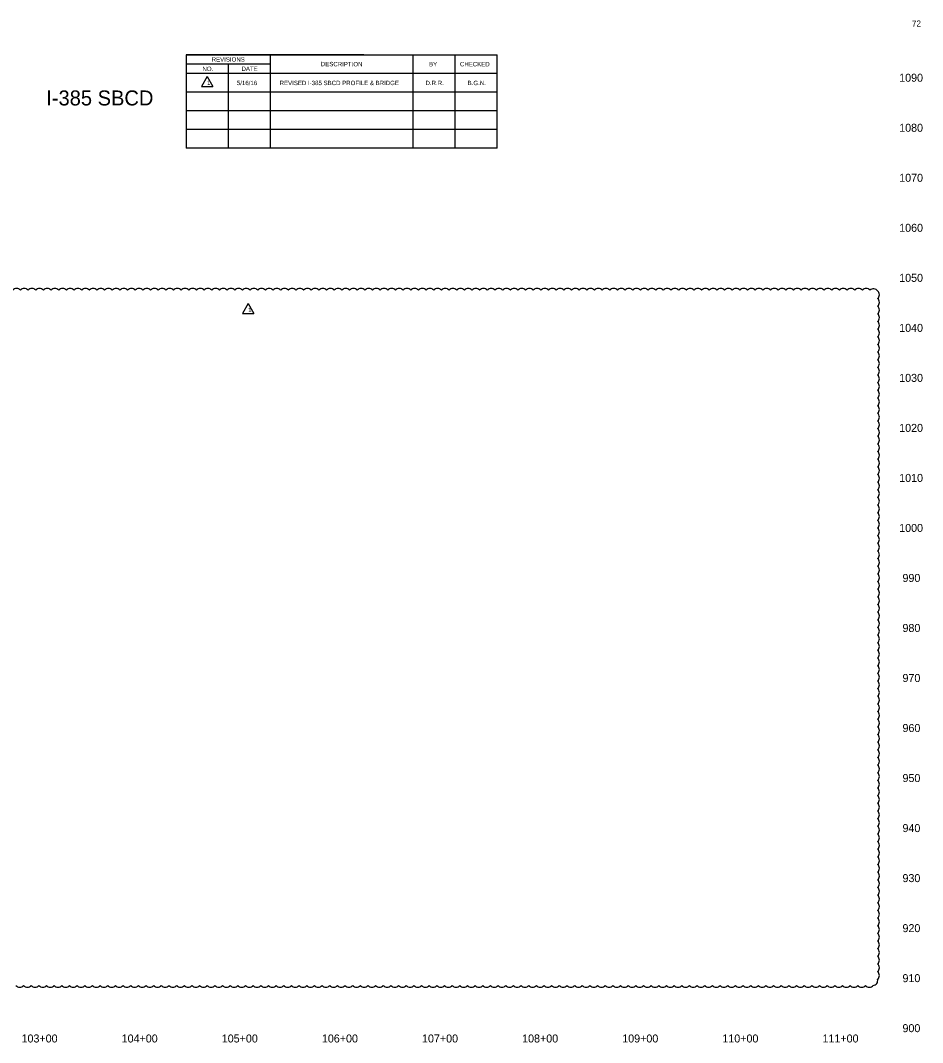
# Model space of a CAD drawing. Extents: x 16972803 to 16974463, y 12564277 to 12565299.
# Drawn here: x 16973562 to 16974463, y 12564277 to 12565299 of the extents above; entities that cross this region are included whole.
import ezdxf

# ---------------------------------------------------------------- set-up
doc = ezdxf.new("R2010")
doc.units = 0
for name, color, linetype in [('RD_DDB_ElevTX', 7, 'Continuous'), ('RD_DDB_StaTX', 7, 'Continuous'), ('RD_SHT_TX', 7, 'Continuous')]:
    doc.layers.add(name, color=color, linetype=linetype)

msp = doc.modelspace()

# ---------------------------------------------------------------- linework, layer by layer
at = {"layer": 'RD_SHT_TX'}
for p, q in [((16973728.1, 12565264.8), (16974038.7, 12565264.8)), ((16973905.4, 12565264.8), (16973728.1, 12565264.8)), ((16973728.1, 12565264.8), (16973728.1, 12565171.3)), ((16973812.1, 12565171.3), (16973812.1, 12565264.8)), ((16973954.7, 12565171.3), (16973954.7, 12565264.8)), ((16973996.7, 12565171.3), (16973996.7, 12565264.8)), ((16974038.7, 12565171.3), (16974038.7, 12565264.8)), ((16973812.1, 12565255.4), (16973728.1, 12565255.4)), ((16973770.1, 12565171.3), (16973770.1, 12565255.4)), ((16974038.7, 12565246.1), (16973728.1, 12565246.1)), ((16973748.8, 12565243.1), (16973743.1, 12565233)), ((16973748.8, 12565243.1), (16973754.5, 12565233)), ((16973743.1, 12565233), (16973754.5, 12565233)), ((16974038.7, 12565227.4), (16973728.1, 12565227.4)), ((16974038.7, 12565208.7), (16973728.1, 12565208.7)), ((16974038.7, 12565190), (16973728.1, 12565190)), ((16974038.7, 12565171.3), (16973728.1, 12565171.3)), ((16973789.9, 12565016.1), (16973784.2, 12565006)), ((16973789.9, 12565016.1), (16973795.6, 12565006)), ((16973784.2, 12565006), (16973795.6, 12565006))]:
    msp.add_line(p, q, dxfattribs=at)
for centre, start, end in [((16973558.6, 12565026.3), 40, 140), ((16973566.2, 12565026.3), 40, 140), ((16973573.9, 12565026.3), 40, 140), ((16973581.5, 12565026.3), 40, 140), ((16973589.2, 12565026.3), 40, 140), ((16973596.8, 12565026.3), 40, 140), ((16973604.5, 12565026.3), 40, 140), ((16973612.1, 12565026.3), 40, 140), ((16973619.8, 12565026.3), 40, 140), ((16973627.4, 12565026.3), 40, 140), ((16973635, 12565026.3), 40, 140), ((16973642.7, 12565026.3), 40, 140), ((16973650.3, 12565026.3), 40, 140), ((16973658, 12565026.3), 40, 140), ((16973665.6, 12565026.3), 40, 140), ((16973673.3, 12565026.3), 40, 140), ((16973680.9, 12565026.3), 40, 140), ((16973688.6, 12565026.3), 40, 140), ((16973696.2, 12565026.3), 40, 140), ((16973703.9, 12565026.3), 40, 140), ((16973711.5, 12565026.3), 40, 140), ((16973719.1, 12565026.3), 40, 140), ((16973726.8, 12565026.3), 40, 140), ((16973734.4, 12565026.3), 40, 140), ((16973742.1, 12565026.3), 40, 140), ((16973749.7, 12565026.3), 40, 140), ((16973757.4, 12565026.3), 40, 140), ((16973765, 12565026.3), 40, 140), ((16973772.7, 12565026.3), 40, 140), ((16973780.3, 12565026.3), 40, 140), ((16973787.9, 12565026.3), 40, 140), ((16973795.6, 12565026.3), 40, 140), ((16973803.2, 12565026.3), 40, 140), ((16973810.9, 12565026.3), 40, 140), ((16973818.5, 12565026.3), 40, 140), ((16973826.2, 12565026.3), 40, 140), ((16973833.8, 12565026.3), 40, 140), ((16973841.5, 12565026.3), 40, 140), ((16973849.1, 12565026.3), 40, 140), ((16973856.7, 12565026.3), 40, 140), ((16973864.4, 12565026.3), 40, 140), ((16973872, 12565026.3), 40, 140), ((16973879.7, 12565026.3), 40, 140), ((16973887.3, 12565026.3), 40, 140), ((16973895, 12565026.3), 40, 140), ((16973902.6, 12565026.3), 40, 140), ((16973910.3, 12565026.3), 40, 140), ((16973917.9, 12565026.3), 40, 140), ((16973925.5, 12565026.3), 40, 140), ((16973933.2, 12565026.3), 40, 140), ((16973940.8, 12565026.3), 40, 140), ((16973948.5, 12565026.3), 40, 140), ((16973956.1, 12565026.3), 40, 140), ((16973963.8, 12565026.3), 40, 140), ((16973971.4, 12565026.3), 40, 140), ((16973979.1, 12565026.3), 40, 140), ((16973986.7, 12565026.3), 40, 140), ((16973994.3, 12565026.3), 40, 140), ((16974002, 12565026.3), 40, 140), ((16974009.6, 12565026.3), 40, 140), ((16974017.3, 12565026.3), 40, 140), ((16974024.9, 12565026.3), 40, 140), ((16974032.6, 12565026.3), 40, 140), ((16974040.2, 12565026.3), 40, 140), ((16974047.9, 12565026.3), 40, 140), ((16974055.5, 12565026.3), 40, 140), ((16974063.1, 12565026.3), 40, 140), ((16974070.8, 12565026.3), 40, 140), ((16974078.4, 12565026.3), 40, 140), ((16974086.1, 12565026.3), 40, 140), ((16974093.7, 12565026.3), 40, 140), ((16974101.4, 12565026.3), 40, 140), ((16974109, 12565026.3), 40, 140), ((16974116.7, 12565026.3), 40, 140), ((16974124.3, 12565026.3), 40, 140), ((16974131.9, 12565026.3), 40, 140), ((16974139.6, 12565026.3), 40, 140), ((16974147.2, 12565026.3), 40, 140), ((16974154.9, 12565026.3), 40, 140), ((16974162.5, 12565026.3), 40, 140), ((16974170.2, 12565026.3), 40, 140), ((16974177.8, 12565026.3), 40, 140), ((16974185.5, 12565026.3), 40, 140), ((16974193.1, 12565026.3), 40, 140), ((16974200.7, 12565026.3), 40, 140), ((16974208.4, 12565026.3), 40, 140), ((16974216, 12565026.3), 40, 140), ((16974223.7, 12565026.3), 40, 140), ((16974231.3, 12565026.3), 40, 140), ((16974239, 12565026.3), 40, 140), ((16974246.6, 12565026.3), 40, 140), ((16974254.3, 12565026.3), 40, 140), ((16974261.9, 12565026.3), 40, 140), ((16974269.5, 12565026.3), 40, 140), ((16974277.2, 12565026.3), 40, 140), ((16974284.8, 12565026.3), 40, 140), ((16974292.5, 12565026.3), 40, 140), ((16974300.1, 12565026.3), 40, 140), ((16974307.8, 12565026.3), 40, 140), ((16974315.4, 12565026.3), 40, 140), ((16974323.1, 12565026.3), 40, 140), ((16974330.7, 12565026.3), 40, 140), ((16974338.4, 12565026.3), 40, 140), ((16974346, 12565026.3), 40, 140), ((16974353.6, 12565026.3), 40, 140), ((16974361.3, 12565026.3), 40, 140), ((16974368.9, 12565026.3), 40, 140), ((16974376.6, 12565026.3), 40, 140), ((16974384.2, 12565026.3), 40, 140), ((16974391.9, 12565026.3), 40, 140), ((16974399.5, 12565026.3), 40, 140), ((16974407.2, 12565026.3), 40, 140), ((16974414.4, 12565025.9), 34.0741, 134.0741), ((16974415.4, 12565024.9), 310, 50), ((16974415.4, 12565017.3), 310, 50), ((16974415.4, 12565009.6), 310, 50), ((16974415.4, 12565002), 310, 50), ((16974415.4, 12564994.3), 310, 50), ((16974415.4, 12564986.7), 310, 50), ((16974415.4, 12564979), 310, 50), ((16974415.4, 12564971.4), 310, 50), ((16974415.4, 12564963.8), 310, 50), ((16974415.4, 12564956.1), 310, 50), ((16974415.4, 12564948.5), 310, 50), ((16974415.4, 12564940.8), 310, 50), ((16974415.4, 12564933.2), 310, 50), ((16974415.4, 12564925.5), 310, 50), ((16974415.4, 12564917.9), 310, 50), ((16974415.4, 12564910.2), 310, 50), ((16974415.4, 12564902.6), 310, 50), ((16974415.4, 12564895), 310, 50), ((16974415.4, 12564887.3), 310, 50), ((16974415.4, 12564879.7), 310, 50), ((16974415.4, 12564872), 310, 50), ((16974415.4, 12564864.4), 310, 50), ((16974415.4, 12564856.7), 310, 50), ((16974415.4, 12564849.1), 310, 50), ((16974415.4, 12564841.4), 310, 50), ((16974415.4, 12564833.8), 310, 50), ((16974415.4, 12564826.2), 310, 50), ((16974415.4, 12564818.5), 310, 50), ((16974415.4, 12564810.9), 310, 50), ((16974415.4, 12564803.2), 310, 50), ((16974415.4, 12564795.6), 310, 50), ((16974415.4, 12564787.9), 310, 50), ((16974415.4, 12564780.3), 310, 50), ((16974415.4, 12564772.6), 310, 50), ((16974415.4, 12564765), 310, 50), ((16974415.4, 12564757.4), 310, 50), ((16974415.4, 12564749.7), 310, 50), ((16974415.4, 12564742.1), 310, 50), ((16974415.4, 12564734.4), 310, 50), ((16974415.4, 12564726.8), 310, 50), ((16974415.4, 12564719.1), 310, 50), ((16974415.4, 12564711.5), 310, 50), ((16974415.4, 12564703.8), 310, 50), ((16974415.4, 12564696.2), 310, 50), ((16974415.4, 12564688.6), 310, 50), ((16974415.4, 12564680.9), 310, 50), ((16974415.4, 12564673.3), 310, 50), ((16974415.4, 12564665.6), 310, 50), ((16974415.4, 12564658), 310, 50), ((16974415.4, 12564650.3), 310, 50), ((16974415.4, 12564642.7), 310, 50), ((16974415.4, 12564635), 310, 50), ((16974415.4, 12564627.4), 310, 50), ((16974415.4, 12564619.8), 310, 50), ((16974415.4, 12564612.1), 310, 50), ((16974415.4, 12564604.5), 310, 50), ((16974415.4, 12564596.8), 310, 50), ((16974415.4, 12564589.2), 310, 50), ((16974415.4, 12564581.5), 310, 50), ((16974415.4, 12564573.9), 310, 50), ((16974415.4, 12564566.2), 310, 50), ((16974415.4, 12564558.6), 310, 50), ((16974415.4, 12564550.9), 310, 50), ((16974415.4, 12564543.3), 310, 50), ((16974415.4, 12564535.7), 310, 50), ((16974415.4, 12564528), 310, 50), ((16974415.4, 12564520.4), 310, 50), ((16974415.4, 12564512.7), 310, 50), ((16974415.4, 12564505.1), 310, 50), ((16974415.4, 12564497.4), 310, 50), ((16974415.4, 12564489.8), 310, 50), ((16974415.4, 12564482.1), 310, 50), ((16974415.4, 12564474.5), 310, 50), ((16974415.4, 12564466.9), 310, 50), ((16974415.4, 12564459.2), 310, 50), ((16974415.4, 12564451.6), 310, 50), ((16974415.4, 12564443.9), 310, 50), ((16974415.4, 12564436.3), 310, 50), ((16974415.4, 12564428.6), 310, 50), ((16974415.4, 12564421), 310, 50), ((16974415.4, 12564413.3), 310, 50), ((16974415.4, 12564405.7), 310, 50), ((16974415.4, 12564398.1), 310, 50), ((16974415.4, 12564390.4), 310, 50), ((16974415.4, 12564382.8), 310, 50), ((16974415.4, 12564375.1), 310, 50), ((16974415.4, 12564367.5), 310, 50), ((16974415.4, 12564359.8), 310, 50), ((16974415.4, 12564352.2), 310, 50), ((16974415.4, 12564344.5), 310, 50), ((16973561.7, 12564337.7), 220, 320), ((16973569.4, 12564337.7), 220, 320), ((16973577, 12564337.7), 220, 320), ((16973584.7, 12564337.7), 220, 320), ((16973592.3, 12564337.7), 220, 320), ((16973599.9, 12564337.7), 220, 320), ((16973607.6, 12564337.7), 220, 320), ((16973615.2, 12564337.7), 220, 320), ((16973622.9, 12564337.7), 220, 320), ((16973630.5, 12564337.7), 220, 320), ((16973638.2, 12564337.7), 220, 320), ((16973645.8, 12564337.7), 220, 320), ((16973653.5, 12564337.7), 220, 320), ((16973661.1, 12564337.7), 220, 320), ((16973668.7, 12564337.7), 220, 320), ((16973676.4, 12564337.7), 220, 320), ((16973684, 12564337.7), 220, 320), ((16973691.7, 12564337.7), 220, 320), ((16973699.3, 12564337.7), 220, 320), ((16973707, 12564337.7), 220, 320), ((16973714.6, 12564337.7), 220, 320), ((16973722.3, 12564337.7), 220, 320), ((16973729.9, 12564337.7), 220, 320), ((16973737.6, 12564337.7), 220, 320), ((16973745.2, 12564337.7), 220, 320), ((16973752.8, 12564337.7), 220, 320), ((16973760.5, 12564337.7), 220, 320), ((16973768.1, 12564337.7), 220, 320), ((16973775.8, 12564337.7), 220, 320), ((16973783.4, 12564337.7), 220, 320), ((16973791.1, 12564337.7), 220, 320), ((16973798.7, 12564337.7), 220, 320), ((16973806.4, 12564337.7), 220, 320), ((16973814, 12564337.7), 220, 320), ((16973821.6, 12564337.7), 220, 320), ((16973829.3, 12564337.7), 220, 320), ((16973836.9, 12564337.7), 220, 320), ((16973844.6, 12564337.7), 220, 320), ((16973852.2, 12564337.7), 220, 320), ((16973859.9, 12564337.7), 220, 320), ((16973867.5, 12564337.7), 220, 320), ((16973875.2, 12564337.7), 220, 320), ((16973882.8, 12564337.7), 220, 320), ((16973890.4, 12564337.7), 220, 320), ((16973898.1, 12564337.7), 220, 320), ((16973905.7, 12564337.7), 220, 320), ((16973913.4, 12564337.7), 220, 320), ((16973921, 12564337.7), 220, 320), ((16973928.7, 12564337.7), 220, 320), ((16973936.3, 12564337.7), 220, 320), ((16973944, 12564337.7), 220, 320), ((16973951.6, 12564337.7), 220, 320), ((16973959.2, 12564337.7), 220, 320), ((16973966.9, 12564337.7), 220, 320), ((16973974.5, 12564337.7), 220, 320), ((16973982.2, 12564337.7), 220, 320), ((16973989.8, 12564337.7), 220, 320), ((16973997.5, 12564337.7), 220, 320), ((16974005.1, 12564337.7), 220, 320), ((16974012.8, 12564337.7), 220, 320), ((16974020.4, 12564337.7), 220, 320), ((16974028, 12564337.7), 220, 320), ((16974035.7, 12564337.7), 220, 320), ((16974043.3, 12564337.7), 220, 320), ((16974051, 12564337.7), 220, 320), ((16974058.6, 12564337.7), 220, 320), ((16974066.3, 12564337.7), 220, 320), ((16974073.9, 12564337.7), 220, 320), ((16974081.6, 12564337.7), 220, 320), ((16974089.2, 12564337.7), 220, 320), ((16974096.8, 12564337.7), 220, 320), ((16974104.5, 12564337.7), 220, 320), ((16974112.1, 12564337.7), 220, 320), ((16974119.8, 12564337.7), 220, 320), ((16974127.4, 12564337.7), 220, 320), ((16974135.1, 12564337.7), 220, 320), ((16974142.7, 12564337.7), 220, 320), ((16974150.4, 12564337.7), 220, 320), ((16974158, 12564337.7), 220, 320), ((16974165.6, 12564337.7), 220, 320), ((16974173.3, 12564337.7), 220, 320), ((16974180.9, 12564337.7), 220, 320), ((16974188.6, 12564337.7), 220, 320), ((16974196.2, 12564337.7), 220, 320), ((16974203.9, 12564337.7), 220, 320), ((16974211.5, 12564337.7), 220, 320), ((16974219.2, 12564337.7), 220, 320), ((16974226.8, 12564337.7), 220, 320), ((16974234.4, 12564337.7), 220, 320), ((16974242.1, 12564337.7), 220, 320), ((16974249.7, 12564337.7), 220, 320), ((16974257.4, 12564337.7), 220, 320), ((16974265, 12564337.7), 220, 320), ((16974272.7, 12564337.7), 220, 320), ((16974280.3, 12564337.7), 220, 320), ((16974288, 12564337.7), 220, 320), ((16974295.6, 12564337.7), 220, 320), ((16974303.2, 12564337.7), 220, 320), ((16974310.9, 12564337.7), 220, 320), ((16974318.5, 12564337.7), 220, 320), ((16974326.2, 12564337.7), 220, 320), ((16974333.8, 12564337.7), 220, 320), ((16974341.5, 12564337.7), 220, 320), ((16974349.1, 12564337.7), 220, 320), ((16974356.8, 12564337.7), 220, 320), ((16974364.4, 12564337.7), 220, 320), ((16974372.1, 12564337.7), 220, 320), ((16974379.7, 12564337.7), 220, 320), ((16974387.3, 12564337.7), 220, 320), ((16974395, 12564337.7), 220, 320), ((16974402.6, 12564337.7), 220, 320), ((16974410.3, 12564337.7), 220, 320), ((16974413.7, 12564339.5), 274.0608, 14.0608)]:
    msp.add_arc(centre, 4.99, start, end, dxfattribs=at)

# ---------------------------------------------------------------- texts
at = {"layer": 'RD_DDB_ElevTX'}
for s, p in [('1090', (16974440.1, 12565237.8)), ('1080', (16974440.1, 12565187.8)), ('1070', (16974440.1, 12565137.8)), ('1060', (16974440.1, 12565087.8)), ('1050', (16974440.1, 12565037.8)), ('1040', (16974440.1, 12564987.8)), ('1030', (16974440.1, 12564937.8)), ('1020', (16974440.1, 12564887.8)), ('1010', (16974440.1, 12564837.8)), ('1000', (16974440.1, 12564787.8)), ('990', (16974443.4, 12564737.8)), ('980', (16974443.4, 12564687.8)), ('970', (16974443.4, 12564637.8)), ('960', (16974443.4, 12564587.8)), ('950', (16974443.4, 12564537.8)), ('940', (16974443.4, 12564487.8)), ('930', (16974443.4, 12564437.8)), ('920', (16974443.4, 12564387.8)), ('910', (16974443.4, 12564337.8)), ('900', (16974443.4, 12564287.8))]:
    msp.add_text(s, height=8, dxfattribs=at).set_placement(p)
at = {"layer": 'RD_DDB_StaTX'}
for s, p in [('103+00', (16973563.5, 12564277.5)), ('104+00', (16973663.5, 12564277.5)), ('105+00', (16973763.5, 12564277.5)), ('106+00', (16973863.5, 12564277.5)), ('107+00', (16973963.5, 12564277.5)), ('108+00', (16974063.5, 12564277.5)), ('109+00', (16974163.5, 12564277.5)), ('110+00', (16974263.5, 12564277.5)), ('111+00', (16974363.5, 12564277.5))]:
    msp.add_text(s, height=8, dxfattribs=at).set_placement(p)
at = {"layer": 'RD_SHT_TX'}
for s, height, p in [('72', 6, (16974452.9, 12565293)), ('REVISIONS', 4.4, (16973753.4, 12565257.9)), ('NO.', 4.4, (16973744.2, 12565248.5)), ('CHECKED', 4.4, (16974001.4, 12565253.2)), ('1', 4.4, (16973748.8, 12565234.6)), ('5/16/16', 4.4, (16973778.6, 12565234.4)), ('REVISED I-385 SBCD PROFILE & BRIDGE', 4.4, (16973821.3, 12565234.4)), ('D.R.R.', 4.4, (16973967, 12565234.4)), ('B.G.N.', 4.4, (16974009.1, 12565234.4)), ('I-385 SBCD', 15, (16973588.2, 12565214.1)), ('1', 4.4, (16973789.9, 12565007.6))]:
    msp.add_text(s, height=height, dxfattribs=at).set_placement(p)
for s, height, p in [('DATE', 4.41, (16973783.2, 12565248.6)), ('DESCRIPTION', 4.408, (16973862.4, 12565253.3)), ('BY', 4.41, (16973970.5, 12565253.2))]:
    msp.add_text(s, height=height, rotation=359.7246, dxfattribs=at).set_placement(p)

doc.saveas('drawing.dxf')
